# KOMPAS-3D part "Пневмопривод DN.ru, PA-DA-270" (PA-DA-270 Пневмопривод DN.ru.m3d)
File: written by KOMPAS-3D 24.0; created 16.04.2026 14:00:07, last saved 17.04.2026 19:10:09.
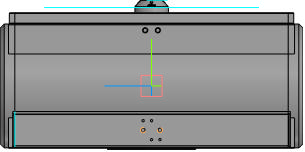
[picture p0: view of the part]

Document properties: Автор: DN.ru; Полное имя файла: C:\Работа\PA-DA-х Пневмопривод DN.ru\270\исходные материалы\PA-DA-270 Пневмопривод DN.ru.m3d

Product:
- Body: Тело 1  | qty 1
    Масса: 460.629606
- Body: Тело 2  | qty 1
    Масса: 460.629606
- Part/product: Пневмопривод DN.ru  | designation PA-DA-270
    Масса: 97
    Раздел спецификации: Прочие изделия
    Примечание: D290-00301

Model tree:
1. Эскиз:1
2. Элемент выдавливания:1
3. Эскиз:2  (with: Ребро.Элемент выдавливания:1)
4. Элемент выдавливания:2
5. Эскиз:3  (with: Ребро.Элемент выдавливания:2)
6. Элемент выдавливания:3  (with: Грань.Элемент выдавливания:2)
     Смещение 1 = -2; Расстояние 2 = 337; Смещение 2 = -2
7. Эскиз:4  (with: Грань.Элемент выдавливания:3)
8. Элемент выдавливания:4
9. Эскиз:6  (with: Ребро.Элемент выдавливания:2)
10. Элемент выдавливания:6
11. Отверстие:2  (with: Грань.Элемент выдавливания:6)
     Глубина выреза = 10; Диаметр отверстия = 6; Угол конуса дна = 120; Расстояние 2 = 17.5
12. Массив по сетке:2  (with: Отверстие:2)  (3 pattern instances)
     Шаг 1 = 20; Угол раствора = 90; Шаг 2 = 45
13. Массив по сетке:3  (with: Отверстие:2)  (2 pattern instances)
     Шаг 1 = 45; Угол раствора = 90; Шаг 2 = 20
14. Отверстие:3  (with: Грань.Элемент выдавливания:6, Ребро.Элемент выдавливания:6)  (labels: W 1/2'')
     Глубина выреза = 10; Диаметр отверстия = 9.98886; Угол конуса дна = 120; Расстояние 1 = 20; Расстояние 2 = 40
15. W 1/2''  (with: Грань.Отверстие:3, Грань.Элемент выдавливания:6)  (labels: cil5_ex_DIN 477 BSW coarse)
     Длина резьбы = 8; Шаг резьбы = 2.117; Номинальный диаметр резьбы = 12.7
16. Массив по сетке:4  (with: Отверстие:3)  (labels: W 1/2'')  (2 pattern instances)
17. W 1/4''  (with: Грань.Отверстие:3, Грань.Элемент выдавливания:6)  (labels: cil5_ex_DIN 477 BSW coarse)
     Длина резьбы = 8; Шаг резьбы = 2.117; Номинальный диаметр резьбы = 12.7; Шаг 1 = 40; Угол раствора = 90; Шаг 2 = 10
18. Эскиз:7  (with: Грань.Элемент выдавливания:2)
19. Элемент выдавливания:7
20. Эскиз:8  (with: Грань.Элемент выдавливания:2, Ребро.Элемент выдавливания:2)
21. Элемент выдавливания:8  (with: Грань.Элемент выдавливания:6)
     Расстояние 2 = 4
22. Отверстие:4  (with: Грань.Элемент выдавливания:2)
     Глубина выреза = 7; Диаметр отверстия = 10; Угол конуса дна = 118; Расстояние 1 = 15; Расстояние 2 = 15; Диаметр зенковки = 13.2; Глубина зенковки = 1.6; Угол зенковки = 90
23. Массив по сетке:5  (with: Отверстие:4)  (2 pattern instances)
     Шаг 1 = 30; Угол раствора = 90
24. Отверстие:5  (with: Грань.Элемент выдавливания:3)
     Глубина выреза = 10; Диаметр отверстия = 5; Угол конуса дна = 120; Диаметр зенковки = 7; Глубина зенковки = 1; Угол зенковки = 90
25. Массив по сетке:6  (with: Отверстие:5)  (4 pattern instances)
     Угол раствора = 90
26. Фаска:1  (with: Ребро.Элемент выдавливания:4)
     Угол = 45; Длина 1 = 15; Длина 2 = 15
27. Скругление:2  (with: Ребро.Элемент выдавливания:3)
     Радиус = 2
28. Скругление:3  (with: Ребро.Элемент выдавливания:6)
     Радиус = 3
29. Скругление:4  (with: Ребро.Элемент выдавливания:8, Ребро.Элемент выдавливания:2)
     Радиус = 2
30. Скругление:5  (with: Ребро.Элемент выдавливания:6)
     Радиус = 3
31. Смещенная плоскость:1  (with: Грань.Элемент выдавливания:3)
32. Эскиз:9
33. Элемент выдавливания:9  (with: Грань.Фаска:1)
     Расстояние 1 = 43.4142; Смещение 1 = 1
34. Смещенная плоскость:2  (with: Грань.Элемент выдавливания:4)
     Расстояние = 0.5
35. Эскиз:10
36. Элемент выдавливания:10
     Расстояние 1 = 25.9142
37. Эскиз:11  (with: Грань.Элемент выдавливания:4)
38. Элемент выдавливания:11
     Расстояние 1 = 1
39. Эскиз:12  (with: Грань.Элемент выдавливания:11, Ребро.Элемент выдавливания:11)
40. Элемент выдавливания:12  (with: Грань.Элемент выдавливания:4)
     Расстояние 2 = 1
41. Эскиз:13  (with: Грань.Элемент выдавливания:11)
42. Элемент выдавливания:13  (with: Грань.Элемент выдавливания:4)
     Расстояние 2 = 1
43. Скругление:7  (with: Ребро.Элемент выдавливания:11)
     Радиус = 1
44. Скругление:8  (with: Ребро.Элемент выдавливания:8)
     Радиус = 2
45. Эскиз:14  (with: Грань.Элемент выдавливания:3)
46. Элемент выдавливания:14  (with: Грань.Фаска:1)
     Расстояние 1 = 54.1414; Смещение 1 = 0.1
47. Эскиз:15  (with: Грань.Элемент выдавливания:3, Ребро.Скругление:2)
48. Элемент выдавливания:15
     Расстояние 2 = 0.1
49. Отверстие:6  (with: Грань.Элемент выдавливания:2, Ребро.Элемент выдавливания:2)
     Глубина выреза = 10; Диаметр отверстия = 10; Угол конуса дна = 118; Расстояние 1 = 20; Расстояние 2 = 20; Диаметр цековки = 20; Глубина цековки = 5
50. Зеркальный массив:1
51. Экземпляр ( 1 )
52. Экземпляр ( 2 )  (with: Отверстие:6)
53. Зеркальный массив:2  (with: Экземпляр ( 1 ), Экземпляр ( 2 ), Отверстие:6)
54. Зеркальный массив:3  (with: Экземпляр ( 1 ), Экземпляр ( 2 ), Зеркальный массив:2, Отверстие:6)
55. Зеркальный массив:4  (with: Экземпляр ( 1 ), Экземпляр ( 2 ), Зеркальный массив:1, Отверстие:6, Зеркальный массив:3, Зеркальный массив:2)
56. Фаска:2  (with: Ребро.Элемент выдавливания:7)
     Угол = 45; Длина 1 = 2.5; Длина 2 = 2.5
57. Фаска:3  (with: Ребро.Элемент выдавливания:1)
     Угол = 45; Длина 1 = 10; Длина 2 = 10
58. Смещенная плоскость:3  (with: Грань.Элемент выдавливания:6)
     Расстояние = 5
59. Эскиз:16
60. Элемент выдавливания:16
     Расстояние 2 = 0.1
61. Зеркальный массив:5  (with: Экземпляр ( 1 ), Экземпляр ( 2 ), Элемент выдавливания:16)

Expressions: H/2; -G/2; v2053*2; (E-D-6)/2
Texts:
  PA-DA-270
  GOST 26.020 Pr3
